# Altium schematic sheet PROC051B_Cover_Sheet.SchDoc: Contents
size 431 x 279 mm; Date: Not shown in title block; ApprovedBy: Not shown in title block; CheckedBy: Not shown in title block; Author: Not shown in title block; CompanyName: Not shown in title block; Engineer: Not shown in title block; Organization: Not shown in title block; Address1: Not shown in title block; Address2: Not shown in title block; Address3: Not shown in title block; Address4: Not shown in title block; DocumentNumber: 1; Revision: Use project parameter SCH_Rev; SheetNumber: 1; SheetTotal: 16; PageSetup: Record=PageOptions¦CenterHorizontal=True¦CenterVertical=True¦PrintScale=0.64¦XCorrection=1.00¦YCorrection=1.00¦PrintKind=0¦BorderSize=5000000¦LeftOffset=0¦BottomOffset=0¦Orientation=2¦PaperLength=1000¦PaperWidth=1000¦Scale=100¦PaperSource=15¦PrintQuality=600¦MediaType=1¦DitherType=10¦PrintScaleMode=1¦PaperKind=Letter
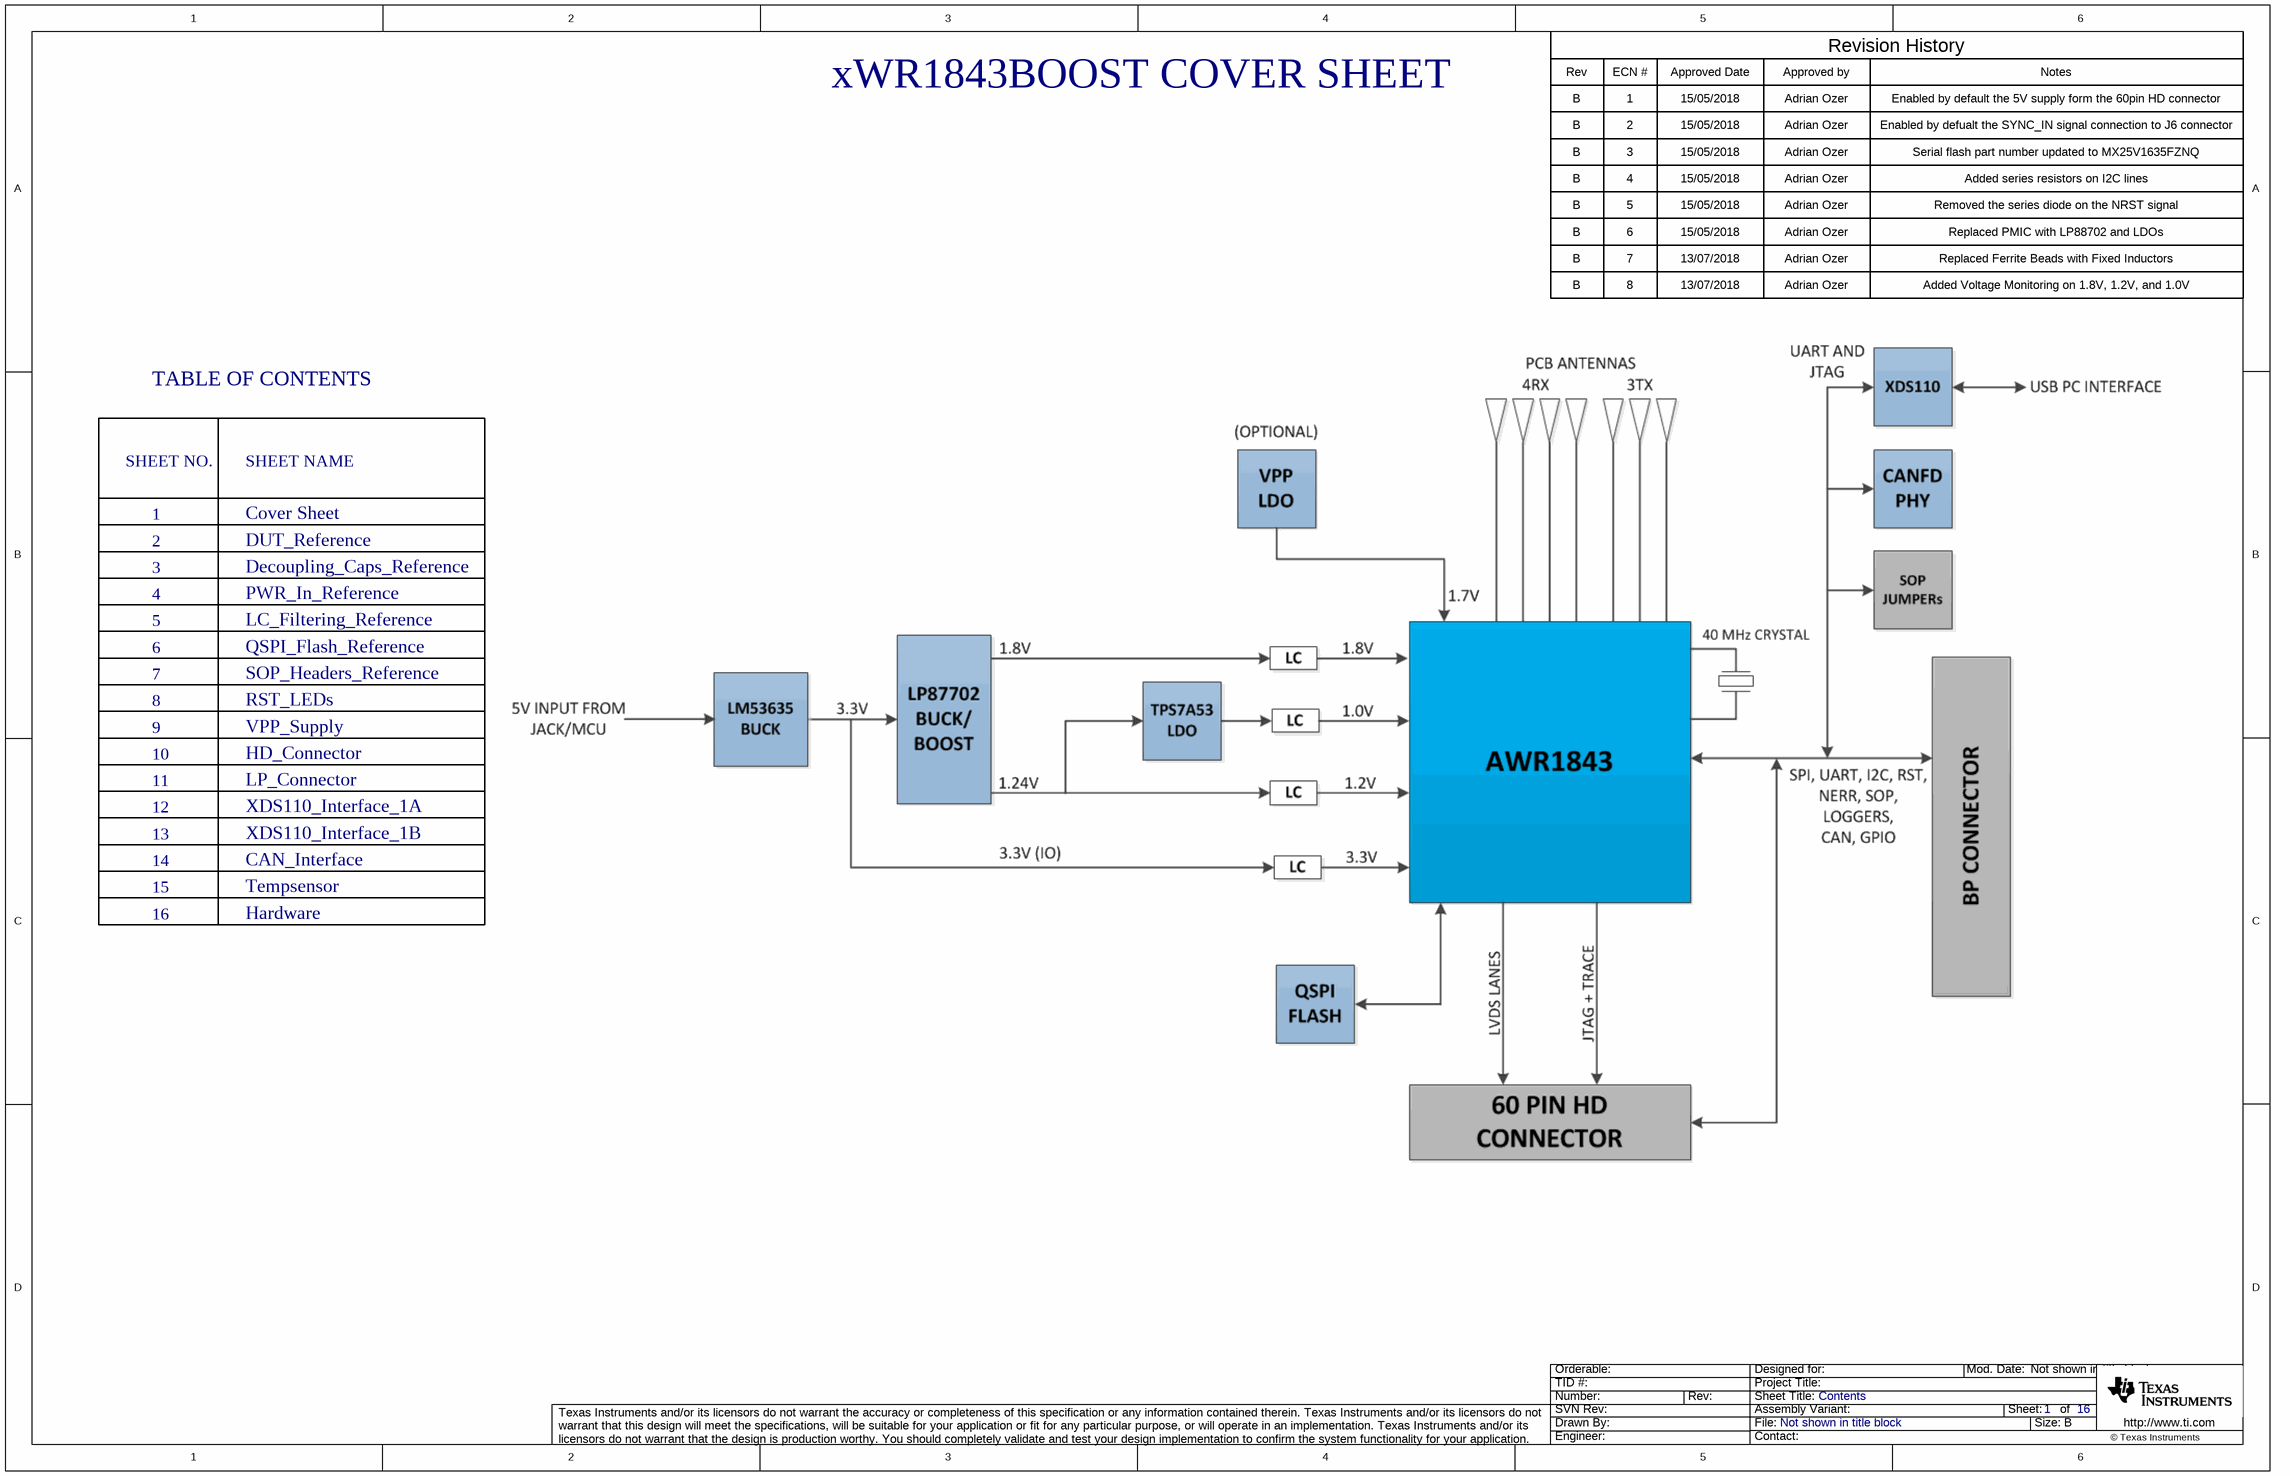
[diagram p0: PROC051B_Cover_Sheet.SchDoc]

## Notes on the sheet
- xWR1843BOOST COVER SHEET
- Rev
- B
- ECN #
- 1
- Approved Date
- 15/05/2018
- Approved by
- Adrian Ozer
- Revision History
- Notes
- Enabled by default the 5V supply form the 60pin HD connector
- 2
- 3
- Enabled by defualt the SYNC_IN signal connection to J6 connector
- Serial flash part number updated to MX25V1635FZNQ
- 4
- 5
- 6
- Added series resistors on I2C lines
- Removed the series diode on the NRST signal
- Replaced PMIC with LP88702 and LDOs
- 7
- 8
- 13/07/2018
- Replaced Ferrite Beads with Fixed Inductors
- Added Voltage Monitoring on 1.8V, 1.2V, and 1.0V
- TABLE OF CONTENTS
- SHEET NO.
- SHEET NAME
- Cover Sheet
- DUT_Reference
- Decoupling_Caps_Reference
- PWR_In_Reference
- LC_Filtering_Reference
- QSPI_Flash_Reference
- SOP_Headers_Reference
- 9
- 10
- RST_LEDs
- VPP_Supply
- HD_Connector
- 11
- 12
- LP_Connector
- XDS110_Interface_1A
- 13
- 15
- 14
- XDS110_Interface_1B
- Tempsensor
- CAN_Interface
- 16
- Hardware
